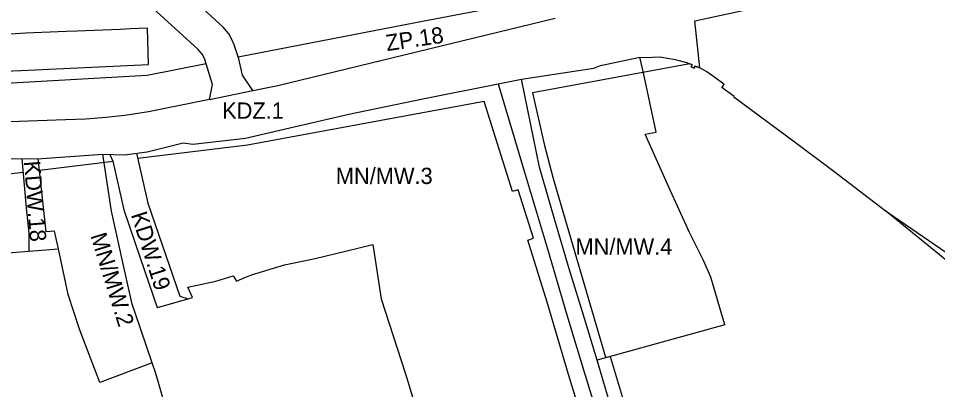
# Model space of a CAD drawing. Extents: x 7426178 to 7427732, y 5548847 to 5550287.
# Drawn here: x 7426699.7 to 7426953.6, y 5549904.6 to 5550007.1 of the extents above; entities that cross this region are included whole.
import ezdxf

# ---------------------------------------------------------------- set-up
doc = ezdxf.new("R2010")
doc.units = 0
for name, color, linetype in [('linie_rozgraniczajace', 7, 'Continuous'), ('linie_zabudowy_nieprzekraczalne', 7, 'Continuous'), ('linie_zabudowy_obowiazujace', 7, 'Continuous'), ('oznaczenia_przeznaczen', 7, 'Continuous')]:
    doc.layers.add(name, color=color, linetype=linetype)

msp = doc.modelspace()

# ---------------------------------------------------------------- linework, layer by layer
at = {"layer": 'linie_rozgraniczajace'}
for p, q in [((7426752.52, 5549984.69), (7426764.47, 5549987.16)), ((7426894.81, 5549922.48), (7426859.57, 5549912.74))]:
    msp.add_line(p, q, dxfattribs=at)
for points in [[(7426887.92, 5549993.43), (7426886.51, 5550006.42), (7426914.36, 5550012.51), (7426934.23, 5550022.99), (7426946.05, 5550033.97), (7426953.35, 5550044.79), (7426958.54, 5550057.29), (7426961.53, 5550071.48), (7426969, 5550191.04)], [(7426764.47, 5549987.16), (7426761.6, 5549991.44), (7426760.59, 5549995.93), (7426759.34, 5549999.85), (7426758.66, 5550001.3), (7426757.82, 5550002.88), (7426756.26, 5550004.7), (7426746.41, 5550013.86), (7426744.49, 5550015.72), (7426743.35, 5550017.56), (7426742.79, 5550019.48), (7426742.7, 5550021.41), (7426743.21, 5550023.25), (7426744, 5550024.83), (7426745.48, 5550026.7), (7426747.84, 5550028.95), (7426751.03, 5550031.35), (7426752.89, 5550032.4), (7426754.02, 5550032.82)], [(7426865.33, 5550016.92), (7426847.7, 5550013.27), (7426809.4, 5550005.92), (7426760.45, 5549996.38)], [(7426752.52, 5549984.69), (7426753.36, 5549988.87), (7426751.24, 5549995.76), (7426750.53, 5549997.13), (7426749.32, 5549998.59), (7426735.86, 5550010.83), (7426734.65, 5550011.7), (7426733.73, 5550012), (7426732.04, 5550012.3), (7426727.73, 5550012.55), (7426716.9, 5550012.11), (7426698.65, 5550011.25), (7426689.41, 5550010.96), (7426675.52, 5550010.4), (7426656.51, 5550009.38)], [(7426764.47, 5549987.16), (7426771.4, 5549988.6), (7426847.94, 5550007.19)], [(7426633.79, 5549966.33), (7426649.53, 5549967.29), (7426668.68, 5549968.13), (7426688.03, 5549968.31), (7426706.22, 5549968.4), (7426723.03, 5549969.59), (7426729.06, 5549969.47), (7426735.25, 5549970.26), (7426745.25, 5549972.76), (7426747.88, 5549972.38), (7426762.4, 5549974), (7426774.65, 5549976.92), (7426791, 5549980.65), (7426811.41, 5549984.86), (7426832.18, 5549989.03), (7426838.63, 5549990.38), (7426858.66, 5549993.37), (7426860.43, 5549994.11), (7426871.32, 5549996.43)], [(7426871.32, 5549996.43), (7426872.72, 5549996.32), (7426874.83, 5549996.42), (7426876.95, 5549996.52), (7426879.02, 5549996.18), (7426881.08, 5549995.81), (7426882.21, 5549995.51), (7426883.21, 5549995.23), (7426884.2, 5549994.94), (7426884.99, 5549994.63), (7426885.78, 5549994.33), (7426885.52, 5549993.72), (7426886.3, 5549993.38), (7426886.56, 5549993.97), (7426887.92, 5549993.43)], [(7426879.34, 5549960.51), (7426872.85, 5549975.14), (7426875.89, 5549975.68), (7426872.32, 5549992.1), (7426871.32, 5549996.43)], [(7426653.91, 5549986.82), (7426735.24, 5549991.47), (7426751.58, 5549994.65)], [(7426957.62, 5549941.24), (7426941.5, 5549952.34), (7426939.11, 5549953.98), (7426924.93, 5549964.83), (7426913.98, 5549973.04), (7426897.27, 5549985.34), (7426897.38, 5549985.5), (7426893.99, 5549988.01), (7426894.64, 5549988.87), (7426894.5, 5549988.97), (7426892.03, 5549990.78), (7426889.83, 5549992.35), (7426887.92, 5549993.43)], [(7426832.18, 5549989.03), (7426839.49, 5549964.6), (7426845.83, 5549943.49), (7426851.15, 5549925.23), (7426855.77, 5549910), (7426863.95, 5549883.29)], [(7426859.57, 5549912.74), (7426855.41, 5549926.38), (7426851.8, 5549937.95), (7426847.82, 5549951.36), (7426843.63, 5549965.99), (7426838.63, 5549990.38)], [(7426752.52, 5549984.69), (7426735.64, 5549981.28), (7426729.09, 5549980.26), (7426723.9, 5549979.71), (7426718.32, 5549979.29), (7426712.72, 5549979.08), (7426684.7, 5549978.13), (7426678.97, 5549977.95)], [(7426700.65, 5549968.37), (7426701.9, 5549954.76), (7426702.62, 5549947.82)], [(7426709.73, 5549948.37), (7426707.35, 5549948.19), (7426705.18, 5549968.39)], [(7426732.05, 5549925.48), (7426731.12, 5549928.2), (7426728.39, 5549940.56), (7426726.92, 5549947.2), (7426725.45, 5549953.83), (7426723.03, 5549969.59)], [(7426724.99, 5549969.55), (7426725.84, 5549967.7), (7426728.87, 5549954.27), (7426733.36, 5549940.95), (7426738.05, 5549927.24)], [(7426732.33, 5549969.89), (7426735.51, 5549956.11), (7426744.26, 5549930.37), (7426746.57, 5549929.63)], [(7426894.81, 5549922.48), (7426890.93, 5549935.62), (7426888.92, 5549940.2), (7426885.09, 5549947.97), (7426879.34, 5549960.51)], [(7426716.61, 5549921.27), (7426713.43, 5549930.85), (7426710.77, 5549943.44), (7426709.73, 5549948.37)], [(7426702.62, 5549947.82), (7426702.63, 5549942.81)], [(7426693.36, 5549918.54), (7426691.51, 5549923.57), (7426690.58, 5549929.97), (7426689.72, 5549941.8), (7426710.77, 5549943.44)], [(7426747.8, 5549929.98), (7426746.54, 5549932.88), (7426754.28, 5549934.55), (7426759.08, 5549936), (7426759.92, 5549934.53), (7426762.27, 5549935.53), (7426764.08, 5549936.25), (7426773.17, 5549939.01), (7426781.69, 5549940.78), (7426790.09, 5549942.81)], [(7426790.09, 5549942.81), (7426797.59, 5549944.63), (7426799.94, 5549929.65), (7426806.51, 5549909.21), (7426812.16, 5549890.84), (7426824.57, 5549858.44)], [(7426738.05, 5549927.24), (7426739.81, 5549927.69), (7426747.8, 5549929.98)], [(7426736.68, 5549911.95), (7426732.05, 5549925.48)], [(7426748.35, 5549869.5), (7426744.18, 5549886.34), (7426737.69, 5549909.01), (7426736.68, 5549911.95), (7426722.25, 5549906.56), (7426716.61, 5549921.27)], [(7426867.89, 5549885.09), (7426863.5, 5549899.25), (7426859.57, 5549912.74)]]:
    msp.add_lwpolyline(points, dxfattribs=at)
at = {"layer": 'linie_zabudowy_nieprzekraczalne'}
for points in [[(7426981.43, 5549919.51), (7426939.19, 5549953.93), (7426939.11, 5549953.98), (7426924.93, 5549964.83), (7426913.98, 5549973.04), (7426897.27, 5549985.34), (7426897.38, 5549985.5), (7426893.99, 5549988.01), (7426894.64, 5549988.87), (7426894.5, 5549988.97), (7426892.03, 5549990.78), (7426889.83, 5549992.35), (7426887.92, 5549993.43)], [(7426841.67, 5549986.58), (7426844.99, 5549972.04), (7426847.36, 5549962.92), (7426861.89, 5549913.58), (7426863.14, 5549913.73), (7426871.44, 5549886.1)], [(7426860.08, 5549881.06), (7426851.6, 5549908.72), (7426845.76, 5549928.77), (7426840.38, 5549945.88), (7426841.93, 5549946.37), (7426837.76, 5549959.78), (7426836.17, 5549959.27), (7426828.36, 5549984.13)]]:
    msp.add_lwpolyline(points, dxfattribs=at)
at = {"layer": 'linie_zabudowy_obowiazujace'}
msp.add_line((7426701, 5549964.51), (7426636, 5549957.18), dxfattribs=at)
for points in [[(7426730.59, 5550004.22), (7426727.85, 5550004.1), (7426715.92, 5550003.62), (7426712.95, 5550003.5), (7426701.77, 5550003.05), (7426698.87, 5550002.89), (7426688.19, 5550002.46), (7426685.33, 5550002.4), (7426674.55, 5550001.96), (7426671.61, 5550001.82), (7426661.17, 5550001.4), (7426658.35, 5550001.29), (7426653.85, 5550001.05), (7426654.06, 5549990.9), (7426700.38, 5549992.77), (7426735.63, 5549994.37), (7426735.4, 5550004.41), (7426730.59, 5550004.22)], [(7426887.92, 5549993.43), (7426886.56, 5549993.97), (7426886.3, 5549993.38), (7426885.52, 5549993.72), (7426885.78, 5549994.33), (7426885.11, 5549994.55), (7426841.67, 5549986.58)], [(7426828.36, 5549984.13), (7426762.95, 5549972.13), (7426732.68, 5549968.41)], [(7426725.87, 5549967.57), (7426705.53, 5549965.07)]]:
    msp.add_lwpolyline(points, dxfattribs=at)

# ---------------------------------------------------------------- texts
at = {"layer": 'oznaczenia_przeznaczen'}
for s, rotation, p in [('ZP.18', 8.4783, (7426801.51, 5549998.06)), ('KDW.18', 274.4921, (7426701.24, 5549967.62)), ('KDW.19', 287.7858, (7426730.75, 5549952.9)), ('MN/MW.2', 287.2416, (7426719.56, 5549947.12))]:
    msp.add_text(s, height=4.5, rotation=rotation, dxfattribs=at).set_placement(p)
for s, p in [('KDZ.1', (7426755.98, 5549979.41)), ('MN/MW.3', (7426787.39, 5549961.37)), ('MN/MW.4', (7426853.57, 5549941.82))]:
    msp.add_text(s, height=4.5, dxfattribs=at).set_placement(p)

doc.saveas('drawing.dxf')
